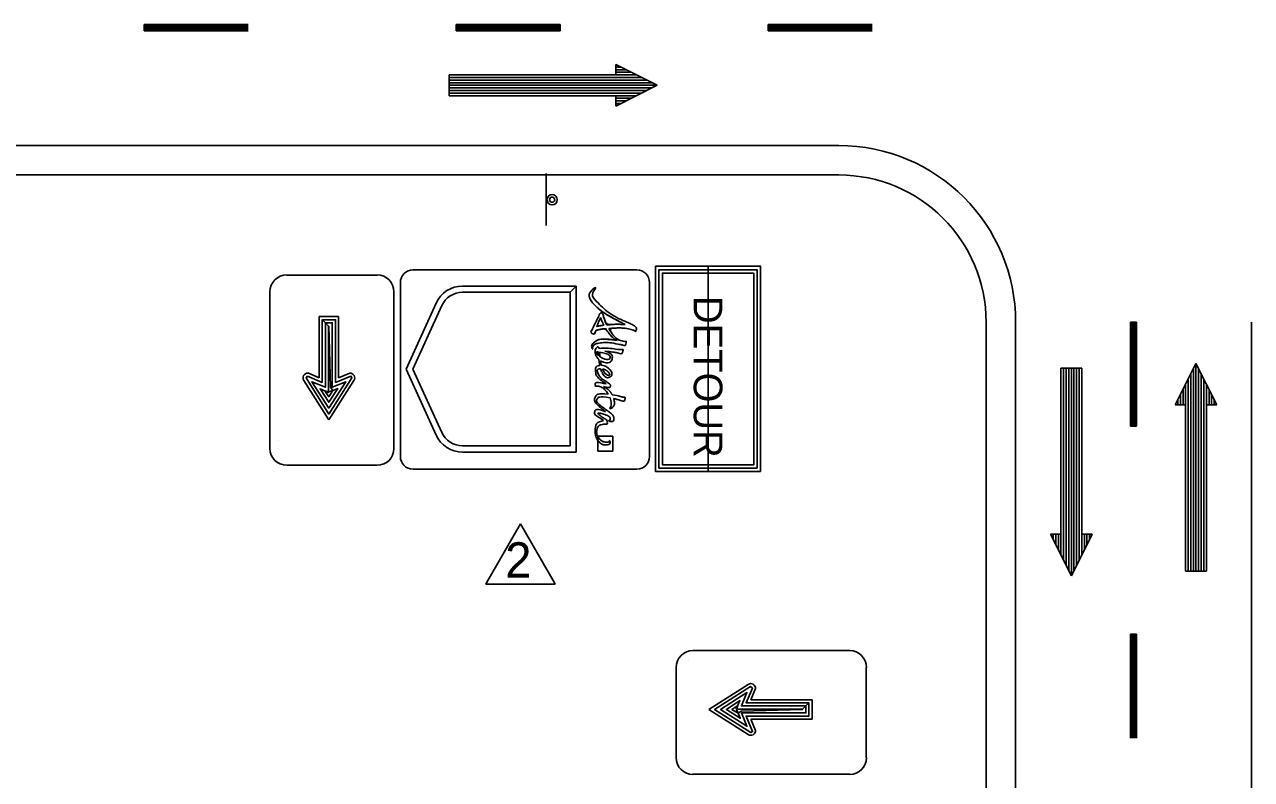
# Model space of a CAD drawing. Extents: x 1482 to 1692, y 225 to 494.
# Drawn here: x 1587.3 to 1637.6, y 351.4 to 382.4 of the extents above; entities that cross this region are included whole.
import ezdxf

# ---------------------------------------------------------------- set-up
doc = ezdxf.new("R2010")
doc.units = 0
for name, color, linetype in [('Level 17', 7, 'Continuous'), ('Level 2', 7, 'Continuous'), ('Level 53', 7, 'Continuous'), ('Level 60', 7, 'Continuous')]:
    doc.layers.add(name, color=color, linetype=linetype)

msp = doc.modelspace()

# ---------------------------------------------------------------- linework, layer by layer
at = {"layer": 'Level 17'}
for p, q in [((1608.697, 376.283), (1608.697, 374.15)), ((1598.055, 372.114), (1601.752, 372.114)), ((1615.334, 372.485), (1615.334, 364.048)), ((1597.358, 364.994), (1597.358, 371.43)), ((1602.438, 371.43), (1602.438, 364.994)), ((1599.376, 370.415), (1599.376, 367.906)), ((1600.176, 370.415), (1599.376, 370.415)), ((1600.176, 367.9), (1600.176, 370.415)), ((1599.376, 367.9), (1598.914, 368.098)), ((1600.636, 368.092), (1600.176, 367.9)), ((1598.748, 367.79), (1599.772, 366.178)), ((1599.772, 366.178), (1600.803, 367.79)), ((1597.706, 365.327), (1597.706, 365.327)), ((1601.752, 364.316), (1598.055, 364.316)), ((1613.152, 363.777), (1613.152, 363.777)), ((1613.152, 363.777), (1613.152, 363.777)), ((1613.152, 363.777), (1613.152, 363.777)), ((1613.152, 363.777), (1613.152, 363.777)), ((1621.149, 356.703), (1614.712, 356.703)), ((1614.028, 356.006), (1614.028, 352.309)), ((1614.516, 356.355), (1614.516, 356.355)), ((1621.827, 352.309), (1621.827, 356.006)), ((1616.979, 355.313), (1615.366, 354.289)), ((1617.088, 354.685), (1617.286, 355.147)), ((1619.604, 354.685), (1617.094, 354.685)), ((1619.604, 353.885), (1619.604, 354.685)), ((1615.366, 354.289), (1616.979, 353.258)), ((1617.28, 353.425), (1617.088, 353.885)), ((1617.088, 353.885), (1619.604, 353.885)), ((1614.712, 351.623), (1621.149, 351.623))]:
    msp.add_line(p, q, dxfattribs=at)
for points in [[(1617.488, 364.054), (1617.488, 372.479), (1613.18, 372.479), (1613.18, 364.054)], [(1617.346, 364.193), (1617.346, 372.338), (1613.32, 372.338), (1613.32, 364.193)], [(1617.206, 364.334), (1617.206, 372.198), (1613.46, 372.198), (1613.46, 364.334)]]:
    msp.add_lwpolyline(points, close=True, dxfattribs=at)
for points in [[(1597.352, 370.24), (1597.352, 370.132)], [(1599.498, 370.28), (1599.498, 367.708), (1598.902, 367.962), (1598.838, 367.894), (1599.772, 366.414), (1600.72, 367.9), (1600.682, 367.97), (1600.048, 367.708), (1600.048, 370.286), (1599.498, 370.28), (1599.632, 370.158), (1599.632, 367.516), (1599.081, 367.739), (1599.772, 366.658), (1600.464, 367.739), (1599.914, 367.516), (1599.914, 370.158), (1599.632, 370.158), (1599.76, 370.024), (1599.76, 367.304), (1599.414, 367.451), (1599.772, 366.894), (1600.137, 367.464), (1599.933, 367.38), (1599.772, 367.126), (1599.612, 367.368), (1599.778, 367.318), (1599.933, 367.38), (1599.843, 367.51), (1599.778, 370.018), (1599.76, 370.024)], [(1599.498, 370.28), (1599.498, 367.708)], [(1615.904, 356.709), (1616.012, 356.709)], [(1619.469, 354.563), (1616.896, 354.563), (1617.152, 355.159), (1617.082, 355.223), (1615.604, 354.289), (1617.088, 353.341), (1617.159, 353.379), (1616.896, 354.013), (1619.475, 354.013), (1619.469, 354.563), (1619.348, 354.429), (1616.704, 354.429), (1616.928, 354.98), (1615.846, 354.289), (1616.928, 353.597), (1616.704, 354.147), (1619.348, 354.147), (1619.348, 354.429), (1619.212, 354.301), (1616.493, 354.301), (1616.64, 354.647), (1616.084, 354.289), (1616.654, 353.924), (1616.57, 354.128), (1616.314, 354.289), (1616.558, 354.449), (1616.506, 354.283), (1616.57, 354.128), (1616.698, 354.218), (1619.206, 354.283), (1619.212, 354.301)], [(1619.469, 354.563), (1616.896, 354.563)]]:
    msp.add_lwpolyline(points, dxfattribs=at)
for radius in [0.213, 0.107]:
    msp.add_circle((1608.936, 375.212), radius, dxfattribs=at)
for centre, radius, start, end in [((1598.05, 371.43), 0.692, 90, 180), ((1601.754, 371.43), 0.692, 0, 90), ((1598.913, 367.897), 0.199, 89.8942, 212.4962), ((1600.635, 367.894), 0.199, 327.5015, 89.8949), ((1598.05, 365), 0.692, 180, 270), ((1601.754, 365), 0.692, 270, 360), ((1614.713, 356.011), 0.692, 90, 180), ((1621.143, 356.011), 0.692, 0, 90), ((1617.086, 355.147), 0.199, 359.8942, 122.4962), ((1617.083, 353.425), 0.199, 237.5015, 359.8949), ((1614.713, 352.307), 0.692, 180, 270), ((1621.143, 352.307), 0.692, 270, 0)]:
    msp.add_arc(centre, radius, start, end, dxfattribs=at)
at = {"layer": 'Level 2'}
for p, q in [((1592.199, 382.403), (1596.466, 382.403)), ((1592.199, 382.147), (1592.199, 382.403)), ((1592.199, 382.339), (1596.466, 382.339)), ((1592.199, 382.275), (1596.466, 382.275)), ((1592.199, 382.211), (1596.466, 382.211)), ((1592.199, 382.147), (1596.466, 382.147)), ((1604.999, 382.403), (1609.265, 382.403)), ((1604.999, 382.147), (1604.999, 382.403)), ((1604.999, 382.339), (1609.265, 382.339)), ((1604.999, 382.275), (1609.265, 382.275)), ((1604.999, 382.211), (1609.265, 382.211)), ((1604.999, 382.147), (1609.265, 382.147)), ((1609.265, 382.147), (1609.265, 382.403)), ((1617.798, 382.403), (1622.065, 382.403)), ((1617.798, 382.147), (1617.798, 382.403)), ((1617.798, 382.339), (1622.065, 382.339)), ((1617.798, 382.275), (1622.065, 382.275)), ((1617.798, 382.211), (1622.065, 382.211)), ((1617.798, 382.147), (1622.065, 382.147)), ((1613.25, 379.907), (1611.544, 380.761)), ((1611.544, 380.761), (1611.544, 380.334)), ((1611.757, 380.654), (1611.544, 380.654)), ((1611.544, 380.334), (1604.717, 380.334)), ((1604.717, 380.334), (1604.717, 379.481)), ((1612.397, 380.334), (1604.717, 380.334)), ((1612.61, 380.227), (1604.717, 380.227)), ((1612.824, 380.121), (1604.717, 380.121)), ((1611.97, 380.547), (1611.544, 380.547)), ((1612.184, 380.441), (1611.544, 380.441)), ((1613.037, 380.014), (1604.717, 380.014)), ((1613.25, 379.907), (1604.717, 379.907)), ((1613.037, 379.801), (1604.717, 379.801)), ((1612.824, 379.694), (1604.717, 379.694)), ((1613.25, 379.907), (1611.544, 379.054)), ((1612.61, 379.587), (1604.717, 379.587)), ((1611.544, 379.481), (1604.717, 379.481)), ((1612.397, 379.481), (1604.717, 379.481)), ((1611.544, 379.481), (1611.544, 379.054)), ((1612.184, 379.374), (1611.544, 379.374)), ((1611.97, 379.267), (1611.544, 379.267)), ((1611.757, 379.161), (1611.544, 379.161)), ((1559.225, 377.436), (1620.696, 377.436)), ((1559.225, 376.227), (1620.696, 376.227)), ((1612.414, 372.328), (1603.227, 372.328)), ((1602.709, 371.81), (1602.709, 364.668)), ((1605.26, 371.668), (1609.928, 371.668)), ((1609.928, 371.668), (1609.673, 371.412)), ((1609.673, 371.412), (1609.928, 371.668)), ((1609.928, 371.668), (1609.928, 364.852)), ((1612.932, 371.81), (1612.932, 364.668)), ((1612.932, 371.81), (1612.932, 364.668)), ((1609.673, 371.412), (1605.26, 371.412)), ((1609.673, 365.108), (1609.673, 371.412)), ((1602.943, 368.26), (1604.175, 370.969)), ((1604.407, 370.863), (1603.223, 368.26)), ((1626.745, 331.052), (1626.745, 370.179)), ((1627.955, 331.153), (1627.955, 370.179)), ((1632.665, 370.179), (1632.665, 365.913)), ((1632.665, 370.179), (1632.921, 370.179)), ((1632.729, 370.179), (1632.729, 365.913)), ((1632.793, 370.179), (1632.793, 365.913)), ((1632.857, 370.179), (1632.857, 365.913)), ((1632.921, 370.179), (1632.921, 365.913)), ((1637.632, 331.153), (1637.632, 370.179)), ((1604.175, 365.551), (1602.943, 368.26)), ((1603.223, 368.26), (1604.407, 365.657)), ((1629.815, 361.476), (1629.815, 368.303)), ((1630.669, 368.303), (1629.815, 368.303)), ((1629.815, 360.623), (1629.815, 368.303)), ((1629.922, 360.41), (1629.922, 368.303)), ((1630.029, 360.196), (1630.029, 368.303)), ((1630.135, 359.983), (1630.135, 368.303)), ((1630.242, 359.77), (1630.242, 368.303)), ((1630.349, 359.983), (1630.349, 368.303)), ((1630.455, 360.196), (1630.455, 368.303)), ((1630.562, 360.41), (1630.562, 368.303)), ((1630.669, 361.476), (1630.669, 368.303)), ((1630.669, 360.623), (1630.669, 368.303)), ((1635.356, 368.494), (1634.503, 366.787)), ((1635.143, 368.067), (1635.143, 359.961)), ((1635.25, 368.281), (1635.25, 359.961)), ((1635.356, 368.494), (1635.356, 359.961)), ((1635.356, 368.494), (1636.21, 366.787)), ((1635.463, 368.281), (1635.463, 359.961)), ((1635.57, 368.067), (1635.57, 359.961)), ((1634.93, 367.641), (1634.93, 359.961)), ((1635.036, 367.854), (1635.036, 359.961)), ((1635.676, 367.854), (1635.676, 359.961)), ((1635.783, 367.641), (1635.783, 359.961)), ((1634.716, 367.214), (1634.716, 366.787)), ((1634.823, 367.427), (1634.823, 366.787)), ((1635.89, 367.427), (1635.89, 366.787)), ((1635.996, 367.214), (1635.996, 366.787)), ((1634.503, 366.787), (1634.93, 366.787)), ((1634.61, 367.001), (1634.61, 366.787)), ((1634.93, 366.787), (1634.93, 359.961)), ((1635.783, 366.787), (1635.783, 359.961)), ((1635.783, 366.787), (1636.21, 366.787)), ((1636.103, 367.001), (1636.103, 366.787)), ((1632.665, 365.913), (1632.921, 365.913)), ((1605.26, 365.108), (1609.673, 365.108)), ((1609.928, 364.852), (1605.26, 364.852)), ((1612.414, 364.15), (1603.227, 364.15)), ((1630.242, 359.77), (1629.389, 361.476)), ((1629.815, 361.476), (1629.389, 361.476)), ((1629.495, 361.263), (1629.495, 361.476)), ((1629.602, 361.049), (1629.602, 361.476)), ((1629.709, 360.836), (1629.709, 361.476)), ((1630.242, 359.77), (1631.095, 361.476)), ((1631.095, 361.476), (1630.669, 361.476)), ((1630.775, 360.836), (1630.775, 361.476)), ((1630.882, 361.049), (1630.882, 361.476)), ((1630.989, 361.263), (1630.989, 361.476)), ((1634.93, 359.961), (1635.783, 359.961)), ((1632.665, 357.38), (1632.665, 353.113)), ((1632.665, 357.38), (1632.921, 357.38)), ((1632.729, 357.38), (1632.729, 353.113)), ((1632.793, 357.38), (1632.793, 353.113)), ((1632.857, 357.38), (1632.857, 353.113)), ((1632.921, 357.38), (1632.921, 353.113))]:
    msp.add_line(p, q, dxfattribs=at)
for centre, radius, start, end in [((1620.697, 370.179), 7.258, 0, 90), ((1620.697, 370.179), 6.048, 0, 90), ((1603.227, 371.81), 0.518, 90, 180), ((1612.414, 371.81), 0.518, 360, 90), ((1605.26, 370.475), 1.193, 90, 155.5432), ((1605.26, 370.475), 0.937, 90, 155.5432), ((1605.26, 366.045), 1.193, 204.4568, 270), ((1605.26, 366.045), 0.937, 204.4568, 270), ((1603.227, 364.668), 0.518, 180, 270), ((1612.414, 364.668), 0.518, 270, 360)]:
    msp.add_arc(centre, radius, start, end, dxfattribs=at)
at = {"layer": 'Level 53'}
msp.add_line((1610.817, 365.33), (1610.817, 365.48), dxfattribs=at)
msp.add_lwpolyline([(1610.817, 365.33), (1610.817, 364.89), (1611.425, 364.89), (1611.425, 365.498), (1610.817, 365.498), (1610.817, 365.48)], dxfattribs=at)
for points, degree in [([(1610.596, 369.143), (1610.606, 369.208), (1610.695, 369.294), (1610.841, 369.32), (1611.105, 369.366), (1611.365, 369.339), (1611.752, 369.261), (1611.826, 369.247), (1611.953, 369.197), (1611.977, 369.356), (1611.985, 369.406), (1611.96, 369.38), (1611.893, 369.394), (1611.604, 369.455), (1611.397, 369.691), (1611.257, 369.928), (1611.587, 369.953), (1611.954, 369.943), (1612.179, 369.881), (1612.369, 369.828), (1612.334, 369.766), (1612.374, 369.843), (1612.416, 369.925), (1612.361, 370.012), (1612.219, 370.083), (1612.078, 370.154), (1611.31, 370.48), (1610.792, 371.001), (1610.527, 371.268), (1610.663, 371.509), (1610.704, 371.557), (1610.737, 371.597), (1610.686, 371.611), (1610.634, 371.562), (1610.401, 371.347), (1610.534, 371.032), (1610.649, 370.917), (1610.966, 370.6), (1611.648, 370.231), (1611.938, 370.082), (1611.775, 370.096), (1611.501, 370.101), (1611.181, 370.07), (1611.102, 370.232), (1611.056, 370.376), (1611.038, 370.444), (1611.019, 370.518), (1610.989, 370.564), (1610.955, 370.565), (1610.917, 370.567), (1610.885, 370.517), (1610.851, 370.446), (1610.791, 370.318), (1610.614, 369.944), (1610.561, 369.852), (1610.515, 369.773), (1610.551, 369.734), (1610.6, 369.711), (1610.664, 369.68), (1610.702, 369.764), (1610.726, 369.845), (1610.834, 369.876), (1610.98, 369.901), (1611.141, 369.918), (1611.258, 369.728), (1611.414, 369.541), (1611.609, 369.433), (1611.446, 369.46), (1610.892, 369.53), (1610.658, 369.355), (1610.607, 369.316), (1610.55, 369.231), (1610.559, 369.148), (1610.563, 369.109), (1610.588, 369.09), (1610.596, 369.094), (1610.604, 369.097), (1610.593, 369.12), (1610.596, 369.143)], 3), ([(1611.257, 369.928), (1611.587, 369.953), (1611.954, 369.943), (1612.179, 369.881), (1612.369, 369.828), (1612.334, 369.766), (1612.374, 369.843), (1612.416, 369.925), (1612.361, 370.012), (1612.219, 370.083), (1612.078, 370.154), (1611.31, 370.48), (1610.792, 371.001), (1610.527, 371.268), (1610.663, 371.509), (1610.704, 371.557), (1610.737, 371.597), (1610.686, 371.611), (1610.634, 371.562), (1610.401, 371.347), (1610.534, 371.032), (1610.649, 370.917), (1610.966, 370.6), (1611.648, 370.231), (1611.938, 370.082)], 3), ([(1611.181, 370.07), (1611.102, 370.232), (1611.056, 370.376), (1611.038, 370.444), (1611.019, 370.518), (1610.989, 370.564), (1610.955, 370.565), (1610.917, 370.567), (1610.885, 370.517), (1610.851, 370.446), (1610.791, 370.318), (1610.614, 369.944), (1610.561, 369.852), (1610.515, 369.773), (1610.551, 369.734), (1610.6, 369.711), (1610.664, 369.68), (1610.702, 369.764), (1610.726, 369.845)], 3), ([(1610.77, 370.007), (1610.8, 370.09), (1610.848, 370.208), (1610.927, 370.362)], 2), ([(1611.062, 370.058), (1610.933, 370.042), (1610.839, 370.026), (1610.77, 370.007)], 2), ([(1610.927, 370.362), (1610.958, 370.278), (1611.003, 370.17), (1611.062, 370.058), (1610.933, 370.042), (1610.839, 370.026), (1610.77, 370.007), (1610.8, 370.09), (1610.848, 370.208), (1610.927, 370.362)], 3), ([(1610.927, 370.362), (1610.958, 370.278), (1611.003, 370.17), (1611.062, 370.058)], 2), ([(1611.938, 370.082), (1611.775, 370.096), (1611.501, 370.101), (1611.181, 370.07)], 2), ([(1610.596, 369.143), (1610.606, 369.208), (1610.695, 369.294), (1610.841, 369.32), (1611.105, 369.366), (1611.365, 369.339), (1611.752, 369.261), (1611.826, 369.247), (1611.953, 369.197), (1611.977, 369.356), (1611.985, 369.406), (1611.96, 369.38), (1611.893, 369.394), (1611.604, 369.455), (1611.397, 369.691), (1611.257, 369.928)], 3), ([(1610.726, 369.845), (1610.834, 369.876), (1610.98, 369.901), (1611.141, 369.918)], 2), ([(1611.141, 369.918), (1611.258, 369.728), (1611.414, 369.541), (1611.609, 369.433)], 2), ([(1611.609, 369.433), (1611.446, 369.46), (1610.892, 369.53), (1610.658, 369.355), (1610.607, 369.316), (1610.55, 369.231), (1610.559, 369.148), (1610.563, 369.109), (1610.588, 369.09), (1610.596, 369.094), (1610.604, 369.097), (1610.593, 369.12), (1610.596, 369.143)], 3), ([(1610.866, 369.1), (1610.844, 369.168), (1610.792, 369.196), (1610.738, 369.108), (1610.701, 369.047), (1610.688, 368.914), (1610.755, 368.779), (1610.779, 368.73), (1610.812, 368.689), (1610.852, 368.654)], 3), ([(1611.099, 368.996), (1611.254, 368.984), (1611.442, 368.959), (1611.618, 368.924), (1611.691, 368.909), (1611.818, 368.859), (1611.842, 369.018), (1611.85, 369.069), (1611.827, 369.061), (1611.758, 369.057), (1611.666, 369.051), (1611.11, 369.153), (1610.866, 369.1)], 3), ([(1610.766, 368.921), (1610.762, 368.943), (1610.763, 368.961), (1610.765, 368.976)], 2), ([(1610.765, 368.976), (1610.773, 368.967), (1610.784, 368.962), (1610.797, 368.962), (1610.805, 368.962), (1610.814, 368.962), (1610.823, 368.961)], 3), ([(1610.834, 368.809), (1610.797, 368.843), (1610.772, 368.881), (1610.766, 368.921)], 2), ([(1610.823, 368.961), (1610.824, 368.927), (1610.828, 368.873), (1610.834, 368.809)], 2), ([(1610.852, 368.654), (1610.862, 368.573), (1610.875, 368.489), (1610.89, 368.412)], 2), ([(1610.9, 368.761), (1610.894, 368.822), (1610.888, 368.887), (1610.883, 368.955)], 2), ([(1610.883, 368.955), (1611.078, 368.93), (1611.349, 368.828), (1611.306, 368.702), (1611.281, 368.629), (1611.052, 368.667), (1610.9, 368.761)], 3), ([(1610.918, 368.604), (1611.102, 368.491), (1611.35, 368.501), (1611.391, 368.666), (1611.44, 368.858), (1611.254, 368.955), (1611.099, 368.996)], 3), ([(1610.95, 368.414), (1610.938, 368.469), (1610.928, 368.533), (1610.918, 368.604)], 2), ([(1610.89, 368.412), (1610.783, 368.399), (1610.701, 368.329), (1610.716, 368.166), (1610.738, 367.936), (1611.021, 367.731), (1611.158, 367.654)], 3), ([(1611.037, 367.541), (1611.113, 367.526), (1611.196, 367.502), (1611.252, 367.5), (1611.312, 367.499), (1611.325, 367.539), (1611.329, 367.555), (1611.339, 367.59), (1611.322, 367.631), (1611.264, 367.672), (1611.128, 367.769), (1610.914, 367.891), (1610.824, 368.076), (1610.759, 368.209), (1610.824, 368.267), (1610.924, 368.27)], 3), ([(1610.924, 368.27), (1610.932, 368.244), (1610.941, 368.221), (1610.95, 368.201), (1611.056, 367.96), (1611.217, 367.877), (1611.315, 367.938), (1611.408, 367.996), (1611.38, 368.162), (1611.242, 368.294), (1611.174, 368.358), (1611.057, 368.408), (1610.95, 368.414)], 3), ([(1611.23, 368.142), (1611.304, 368.061), (1611.299, 368.021), (1611.279, 368.01), (1611.235, 367.987), (1611.082, 368.082), (1610.998, 368.264)], 3), ([(1610.998, 368.264), (1611.081, 368.248), (1611.171, 368.205), (1611.23, 368.142)], 2), ([(1611.158, 367.654), (1611.011, 367.667), (1610.692, 367.763), (1610.708, 367.6), (1610.714, 367.537), (1610.725, 367.564), (1610.78, 367.56), (1610.972, 367.546), (1611.135, 367.386), (1611.236, 367.227)], 3), ([(1611.4, 367.204), (1611.325, 367.333), (1611.201, 367.453), (1611.037, 367.541)], 2), ([(1611.236, 367.227), (1611, 367.255), (1610.789, 367.245), (1610.722, 367.138), (1610.599, 366.942), (1610.923, 366.663), (1611.121, 366.509)], 3), ([(1610.763, 365.668), (1610.763, 365.918), (1610.957, 365.982), (1611.053, 365.994), (1611.117, 366.002), (1611.209, 365.988), (1611.197, 366.099), (1611.188, 366.176), (1611.038, 366.246), (1610.912, 366.343), (1610.803, 366.427), (1610.813, 366.465), (1610.907, 366.445), (1611.023, 366.421), (1611.297, 366.324), (1611.317, 366.212), (1611.327, 366.16), (1611.236, 366.142), (1611.293, 366.118), (1611.349, 366.095), (1611.472, 366.116), (1611.472, 366.232), (1611.472, 366.313), (1611.386, 366.41), (1611.289, 366.489), (1611.204, 366.558), (1610.688, 366.909), (1610.799, 367.056), (1610.851, 367.124), (1611.063, 367.119), (1611.313, 367.076)], 3), ([(1611.313, 367.076), (1611.38, 366.901), (1611.358, 366.756), (1611.319, 366.674), (1611.3, 366.634), (1611.302, 366.628), (1611.347, 366.645), (1611.412, 366.671), (1611.515, 366.811), (1611.468, 367.03), (1611.467, 367.036), (1611.465, 367.041), (1611.464, 367.046)], 3), ([(1611.464, 367.046), (1611.545, 367.028), (1611.627, 367.008), (1611.708, 366.985), (1611.781, 366.965), (1611.908, 366.905), (1611.932, 367.062), (1611.94, 367.112), (1611.916, 367.091), (1611.848, 367.107), (1611.724, 367.138), (1611.562, 367.176), (1611.4, 367.204)], 3), ([(1611.121, 366.509), (1610.945, 366.588), (1610.72, 366.632), (1610.685, 366.514), (1610.645, 366.377), (1610.873, 366.268), (1611.048, 366.141)], 3), ([(1611.048, 366.141), (1610.923, 366.127), (1610.707, 366.043), (1610.707, 365.706), (1610.707, 365.554), (1610.749, 365.426), (1610.817, 365.33)], 3), ([(1610.817, 365.48), (1610.784, 365.536), (1610.763, 365.6), (1610.763, 365.668)], 2), ([(1611.425, 365.498), (1611.425, 365.498), (1610.817, 365.498), (1610.817, 365.498), (1610.817, 365.498), (1610.817, 365.48), (1610.817, 365.48), (1610.896, 365.348), (1611.047, 365.259), (1611.172, 365.26), (1611.279, 365.26), (1611.273, 365.317), (1611.288, 365.31), (1611.332, 365.292), (1611.307, 365.157), (1611.155, 365.15), (1611.027, 365.143), (1610.902, 365.21), (1610.817, 365.33), (1610.817, 365.33), (1610.817, 364.89), (1610.817, 364.89), (1610.817, 364.89), (1611.425, 364.89), (1611.425, 364.89), (1611.425, 364.89), (1611.425, 365.498), (1611.425, 365.498)], 3), ([(1610.817, 365.48), (1610.896, 365.348), (1611.047, 365.259), (1611.172, 365.26), (1611.279, 365.26), (1611.273, 365.317), (1611.288, 365.31), (1611.332, 365.292), (1611.307, 365.157), (1611.155, 365.15), (1611.027, 365.143), (1610.902, 365.21), (1610.817, 365.33)], 3)]:
    msp.add_open_spline(points, degree=degree, dxfattribs=at)
at = {"layer": 'Level 60'}
for points in [[(1607.638, 361.902), (1606.245, 359.477)], [(1609.032, 359.477), (1607.638, 361.902)], [(1606.245, 359.477), (1606.219, 359.432), (1609.058, 359.432), (1609.032, 359.477)]]:
    msp.add_lwpolyline(points, dxfattribs=at)

# ---------------------------------------------------------------- texts
at = {"layer": 'Level 17'}
msp.add_text('DETOUR', height=1.1758, rotation=270, dxfattribs=at).set_placement((1614.746, 371.258))
at = {"layer": 'Level 60'}
msp.add_text('2', height=1.448, rotation=360, dxfattribs=at).set_placement((1607.011, 359.701))

doc.saveas('drawing.dxf')
